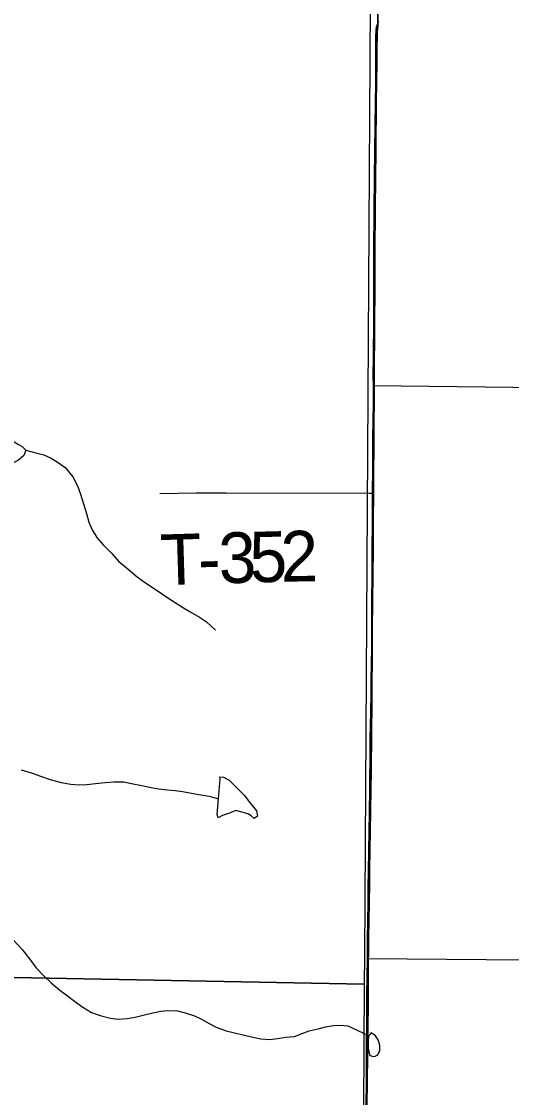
# Model space of a CAD drawing. Extents: x 0 to 34, y 0 to 22.
# Drawn here: x 29.856 to 30.131, y 14.665 to 15.269 of the extents above; entities that cross this region are included whole.
import ezdxf

# ---------------------------------------------------------------- set-up
doc = ezdxf.new("R2010")
doc.units = 0
for name, color, linetype in [('GM_X_County_Road', 7, 'Continuous'), ('GM_X_Minor_Lake', 7, 'Continuous'), ('GM_X_Minor_River', 7, 'Continuous'), ('GM_X_Section', 7, 'Continuous'), ('GM_X_Township_Road', 7, 'Continuous'), ('GM_X_Township_Road_Text', 7, 'Continuous'), ('SC_Scratch1', 7, 'Continuous'), ('SH_Cut_Line', 7, 'Continuous')]:
    doc.layers.add(name, color=color, linetype=linetype)

msp = doc.modelspace()

# ---------------------------------------------------------------- linework, layer by layer
at = {"layer": 'GM_X_County_Road'}
for points in [[(30.05311, 15.06472), (30.05305, 15.06996), (30.05314, 15.08096), (30.05323, 15.08632), (30.05326, 15.09517), (30.05337, 15.10597), (30.05331, 15.11179), (30.05328, 15.11717), (30.05334, 15.12617), (30.05337, 15.13863), (30.0536, 15.16401), (30.054, 15.19681), (30.05437, 15.22371), (30.05454, 15.23339), (30.05445, 15.2468), (30.05445, 15.2556), (30.0545, 15.25848), (30.05456, 15.26105), (30.05465, 15.26299), (30.05469, 15.26408), (30.05484, 15.26591)], [(30.05484, 15.26591), (30.05616, 15.26912)], [(30.05268, 15.00435), (30.05279, 15.01806), (30.05286, 15.02734), (30.05285, 15.03734), (30.05291, 15.04281), (30.05308, 15.05653), (30.05311, 15.06472)], [(30.04979, 14.74345), (30.04981, 14.74448), (30.04985, 14.75606), (30.05002, 14.76263), (30.0502, 14.77634), (30.05026, 14.78298), (30.05043, 14.79275), (30.0506, 14.80359), (30.05067, 14.81497), (30.05083, 14.82489), (30.05105, 14.83899), (30.05118, 14.84699), (30.05125, 14.8518), (30.05137, 14.86599), (30.05154, 14.87484), (30.05158, 14.88079), (30.0518, 14.89294), (30.05193, 14.90072), (30.05201, 14.90687), (30.0522, 14.91952), (30.0522, 14.92857), (30.05232, 14.94239), (30.05243, 14.95928), (30.05247, 14.97158), (30.05262, 14.98869), (30.05268, 15.00435)], [(30.04805, 14.54562), (30.04802, 14.54708), (30.04805, 14.55333), (30.04811, 14.56798), (30.04818, 14.57924), (30.04822, 14.5932), (30.04837, 14.60526), (30.04858, 14.61813), (30.04865, 14.63117), (30.04878, 14.64797), (30.04897, 14.66), (30.04916, 14.67487), (30.04919, 14.68767), (30.04929, 14.69541), (30.04938, 14.70654), (30.04942, 14.71545), (30.04949, 14.72312), (30.04979, 14.74345)]]:
    msp.add_lwpolyline(points, dxfattribs=at)
at = {"layer": 'GM_X_Minor_Lake'}
for points in [[(30.05308, 14.68852), (30.05404, 14.68869), (30.05557, 14.68941), (30.05676, 14.69185), (30.05663, 14.69489), (30.05574, 14.69775), (30.05427, 14.70006), (30.05184, 14.70163), (30.05048, 14.70015), (30.05025, 14.69825)], [(30.05025, 14.69825), (30.05016, 14.69324), (30.05048, 14.69115), (30.05119, 14.68894), (30.05308, 14.68852)]]:
    msp.add_lwpolyline(points, dxfattribs=at)
at = {"layer": 'GM_X_Minor_River'}
for points in [[(29.82367, 15.03636), (29.82542, 15.04848), (29.82998, 15.04853), (29.83288, 15.05015), (29.83515, 15.0497), (29.83776, 15.04792), (29.83992, 15.04386), (29.84133, 15.04021), (29.84466, 15.03726), (29.84838, 15.03449), (29.85138, 15.03307), (29.85381, 15.03167), (29.85586, 15.03047), (29.85808, 15.0285), (29.85685, 15.0255), (29.85393, 15.02293), (29.85123, 15.0215), (29.84742, 15.02123)], [(29.85808, 15.0285), (29.86354, 15.02704), (29.86808, 15.0258), (29.87221, 15.02399), (29.87615, 15.02163), (29.88008, 15.01869), (29.88433, 15.01347), (29.88707, 15.00847), (29.88868, 15.00387), (29.89205, 14.99297), (29.89327, 14.98801), (29.89526, 14.98378), (29.89783, 14.97955), (29.90135, 14.97529), (29.90599, 14.97063), (29.91026, 14.96597), (29.91548, 14.96168), (29.92052, 14.95738), (29.92463, 14.95444), (29.93287, 14.94894), (29.93773, 14.9456), (29.94185, 14.94304), (29.94654, 14.94009), (29.95066, 14.93771), (29.95554, 14.93475), (29.95947, 14.9322), (29.96449, 14.92753)], [(29.85528, 14.84928), (29.86169, 14.84724), (29.86621, 14.84562), (29.87168, 14.84379), (29.87791, 14.84213), (29.88321, 14.84125), (29.88795, 14.84076), (29.89232, 14.84104), (29.89708, 14.8415), (29.9026, 14.84214), (29.90754, 14.8424), (29.91305, 14.84247), (29.9174, 14.84161), (29.92307, 14.84035), (29.92837, 14.83927), (29.93253, 14.83861), (29.93746, 14.83793), (29.94182, 14.83764), (29.94598, 14.83698), (29.9509, 14.83611), (29.9562, 14.83523), (29.96093, 14.83436), (29.96617, 14.83298)], [(29.96617, 14.83298), (29.96703, 14.84408), (29.96687, 14.84522), (29.96896, 14.84516), (29.97214, 14.84335), (29.97528, 14.84022), (29.97841, 14.83709), (29.981, 14.83454), (29.98337, 14.83124), (29.98594, 14.82812), (29.9874, 14.82618), (29.98808, 14.82331), (29.98613, 14.82185), (29.98447, 14.82342), (29.98261, 14.82462), (29.97997, 14.82527)], [(29.96549, 14.82419), (29.96617, 14.83298)], [(29.97997, 14.82527), (29.97582, 14.82634), (29.97236, 14.82493), (29.96833, 14.82353), (29.96601, 14.82227), (29.96549, 14.82419)], [(29.85127, 14.75347), (29.85591, 14.74843), (29.85997, 14.74321), (29.86367, 14.73838), (29.86812, 14.73372), (29.87222, 14.72983), (29.87706, 14.72573), (29.88136, 14.72241), (29.88528, 14.71947), (29.88996, 14.71613), (29.89483, 14.71318), (29.89973, 14.71136), (29.90559, 14.7099), (29.90975, 14.70942), (29.91489, 14.70969), (29.91946, 14.71053), (29.92386, 14.71157), (29.9292, 14.71297), (29.93378, 14.71382), (29.93797, 14.71429), (29.94309, 14.71398), (29.94744, 14.71294), (29.95272, 14.7113), (29.95667, 14.70931), (29.96098, 14.70693), (29.96493, 14.70495), (29.97039, 14.70292), (29.97436, 14.70188), (29.98475, 14.69956), (29.98985, 14.69831), (29.99497, 14.698), (29.99935, 14.69847), (30.00393, 14.69932), (30.00887, 14.69958), (30.01309, 14.70139), (30.01711, 14.70282), (30.02208, 14.70403), (30.02628, 14.70508), (30.03066, 14.70574), (30.03465, 14.70603), (30.03882, 14.70555), (30.04999, 14.70034)], [(30.04999, 14.70034), (30.05048, 14.70015)]]:
    msp.add_lwpolyline(points, dxfattribs=at)
at = {"layer": 'GM_X_Section'}
for points in [[(29.54753, 15.28044), (30.05128, 15.27892), (30.04816, 14.74467), (30.04801, 14.72898), (29.54651, 14.7386)], [(30.04532, 14.23983), (30.04529, 14.22791), (29.54494, 14.23257), (29.54651, 14.7386), (30.04801, 14.72898)]]:
    msp.add_lwpolyline(points, close=True, dxfattribs=at)
at = {"layer": 'GM_X_Township_Road'}
for points in [[(30.05311, 15.06472), (30.19406, 15.06305), (30.19661, 15.06149), (30.19771, 15.05969), (30.19823, 15.05715), (30.19684, 15.014), (30.19777, 15.01122), (30.20055, 15.00902), (30.29943, 15.00793), (30.38475, 15.00663), (30.49976, 15.00557), (30.58521, 15.00485), (30.59836, 15.0043), (30.60774, 15.00311), (30.69999, 14.99043)], [(29.93319, 15.00419), (29.95369, 15.00446), (29.97047, 15.00458), (30.05117, 15.00431), (30.05268, 15.00435)], [(30.04979, 14.74345), (30.42744, 14.74029), (30.69999, 14.73681)]]:
    msp.add_lwpolyline(points, dxfattribs=at)
at = {"layer": 'SC_Scratch1'}
for points in [[(30.05555, 15.27894), (30.05556, 15.26612), (30.05537, 15.26448), (30.05527, 15.26313), (30.05519, 15.26145), (30.05514, 15.25857), (30.0551, 15.25606), (30.05497, 15.24716), (30.05483, 15.23364), (30.05474, 15.22402), (30.05446, 15.19713), (30.05417, 15.16441), (30.05397, 15.13886), (30.05389, 15.1263), (30.05385, 15.1174), (30.05383, 15.11216), (30.05378, 15.10634), (30.05371, 15.09537), (30.05365, 15.08661), (30.05362, 15.08132), (30.0536, 15.07035), (30.05357, 15.06544), (30.05357, 15.06509), (30.05353, 15.05683), (30.05344, 15.04317), (30.05338, 15.03744), (30.05327, 15.02772), (30.05316, 15.01849), (30.05309, 15.00457), (30.05301, 14.98913), (30.05293, 14.97186), (30.05287, 14.9596), (30.05266, 14.94266), (30.05248, 14.9289), (30.05242, 14.91976), (30.05234, 14.90725), (30.05232, 14.90099), (30.05227, 14.89349), (30.05218, 14.88098), (30.05212, 14.87511), (30.05202, 14.86621), (30.05185, 14.85202), (30.0518, 14.8473), (30.05168, 14.83927), (30.05149, 14.82546), (30.05133, 14.81531), (30.05116, 14.80391), (30.05099, 14.79332), (30.05085, 14.78327), (30.05075, 14.77672), (30.05055, 14.76296), (30.05045, 14.75637), (30.05027, 14.74477), (30.05026, 14.74372), (30.05013, 14.72332), (30.05008, 14.71576), (30.04997, 14.70672), (30.04984, 14.6957), (30.04973, 14.688), (30.04955, 14.67516), (30.04942, 14.66034)], [(30.04942, 14.66034), (30.04955, 14.67516), (30.04973, 14.688), (30.04984, 14.6957), (30.04997, 14.70672), (30.05008, 14.71576), (30.05013, 14.72332), (30.05026, 14.74372), (30.05027, 14.74477), (30.05045, 14.75637), (30.05055, 14.76296), (30.05075, 14.77672), (30.05085, 14.78327), (30.05099, 14.79332), (30.05116, 14.80391), (30.05133, 14.81531), (30.05149, 14.82546), (30.05168, 14.83927), (30.0518, 14.8473), (30.05185, 14.85202), (30.05202, 14.86621), (30.05212, 14.87511), (30.05218, 14.88098), (30.05227, 14.89349), (30.05232, 14.90099), (30.05234, 14.90725), (30.05242, 14.91976), (30.05248, 14.9289), (30.05266, 14.94266), (30.05287, 14.9596), (30.05293, 14.97186), (30.05301, 14.98913), (30.05309, 15.00457), (30.05316, 15.01849), (30.05327, 15.02772), (30.05338, 15.03744), (30.05344, 15.04317), (30.05353, 15.05683), (30.05357, 15.06509), (30.05357, 15.06544), (30.0536, 15.07035), (30.05362, 15.08132), (30.05365, 15.08661), (30.05371, 15.09537), (30.05378, 15.10634), (30.05383, 15.11216), (30.05385, 15.1174), (30.05389, 15.1263), (30.05397, 15.13886), (30.05417, 15.16441), (30.05446, 15.19713), (30.05474, 15.22402), (30.05483, 15.23364), (30.05497, 15.24716), (30.0551, 15.25606), (30.05514, 15.25857), (30.05519, 15.26145), (30.05527, 15.26313), (30.05537, 15.26448), (30.05556, 15.26612), (30.05555, 15.27894)]]:
    msp.add_lwpolyline(points, dxfattribs=at)
at = {"layer": 'SH_Cut_Line'}
for points in [[(30.05555, 15.27894), (30.05556, 15.26612), (30.05537, 15.26448), (30.05527, 15.26313), (30.05519, 15.26145), (30.05514, 15.25857), (30.0551, 15.25606), (30.05497, 15.24716), (30.05483, 15.23364), (30.05474, 15.22402), (30.05446, 15.19713), (30.05417, 15.16441), (30.05397, 15.13886), (30.05389, 15.1263), (30.05385, 15.1174), (30.05383, 15.11216), (30.05378, 15.10634), (30.05371, 15.09537), (30.05365, 15.08661), (30.05362, 15.08132), (30.0536, 15.07035), (30.05357, 15.06544), (30.05357, 15.06509), (30.05353, 15.05683), (30.05344, 15.04317), (30.05338, 15.03744), (30.05327, 15.02772), (30.05316, 15.01849), (30.05309, 15.00457), (30.05301, 14.98913), (30.05293, 14.97186), (30.05287, 14.9596), (30.05266, 14.94266), (30.05248, 14.9289), (30.05242, 14.91976), (30.05234, 14.90725), (30.05232, 14.90099), (30.05227, 14.89349), (30.05218, 14.88098), (30.05212, 14.87511), (30.05202, 14.86621), (30.05185, 14.85202), (30.0518, 14.8473), (30.05168, 14.83927), (30.05149, 14.82546), (30.05133, 14.81531), (30.05116, 14.80391), (30.05099, 14.79332), (30.05085, 14.78327), (30.05075, 14.77672), (30.05055, 14.76296), (30.05045, 14.75637), (30.05027, 14.74477), (30.05026, 14.74372), (30.05013, 14.72332), (30.05008, 14.71576), (30.04997, 14.70672), (30.04984, 14.6957), (30.04973, 14.688), (30.04955, 14.67516), (30.04942, 14.66034)], [(30.04942, 14.66034), (30.04955, 14.67516), (30.04973, 14.688), (30.04984, 14.6957), (30.04997, 14.70672), (30.05008, 14.71576), (30.05013, 14.72332), (30.05026, 14.74372), (30.05027, 14.74477), (30.05045, 14.75637), (30.05055, 14.76296), (30.05075, 14.77672), (30.05085, 14.78327), (30.05099, 14.79332), (30.05116, 14.80391), (30.05133, 14.81531), (30.05149, 14.82546), (30.05168, 14.83927), (30.0518, 14.8473), (30.05185, 14.85202), (30.05202, 14.86621), (30.05212, 14.87511), (30.05218, 14.88098), (30.05227, 14.89349), (30.05232, 14.90099), (30.05234, 14.90725), (30.05242, 14.91976), (30.05248, 14.9289), (30.05266, 14.94266), (30.05287, 14.9596), (30.05293, 14.97186), (30.05301, 14.98913), (30.05309, 15.00457), (30.05316, 15.01849), (30.05327, 15.02772), (30.05338, 15.03744), (30.05344, 15.04317), (30.05353, 15.05683), (30.05357, 15.06509), (30.05357, 15.06544), (30.0536, 15.07035), (30.05362, 15.08132), (30.05365, 15.08661), (30.05371, 15.09537), (30.05378, 15.10634), (30.05383, 15.11216), (30.05385, 15.1174), (30.05389, 15.1263), (30.05397, 15.13886), (30.05417, 15.16441), (30.05446, 15.19713), (30.05474, 15.22402), (30.05483, 15.23364), (30.05497, 15.24716), (30.0551, 15.25606), (30.05514, 15.25857), (30.05519, 15.26145), (30.05527, 15.26313), (30.05537, 15.26448), (30.05556, 15.26612), (30.05555, 15.27894)]]:
    msp.add_lwpolyline(points, dxfattribs=at)

# ---------------------------------------------------------------- texts
at = {"layer": 'GM_X_Township_Road_Text'}
for s, rotation, p in [('3', 1.63051, (29.96656, 14.95371)), ('5', 1.47468, (29.98389, 14.95421)), ('2', 0.99385, (30.00119, 14.95465)), ('T', 1.71559, (29.93381, 14.95274)), ('-', 1.69877, (29.95501, 14.95337))]:
    msp.add_text(s, height=0.02841, rotation=rotation, dxfattribs=at).set_placement(p)

doc.saveas('drawing.dxf')
